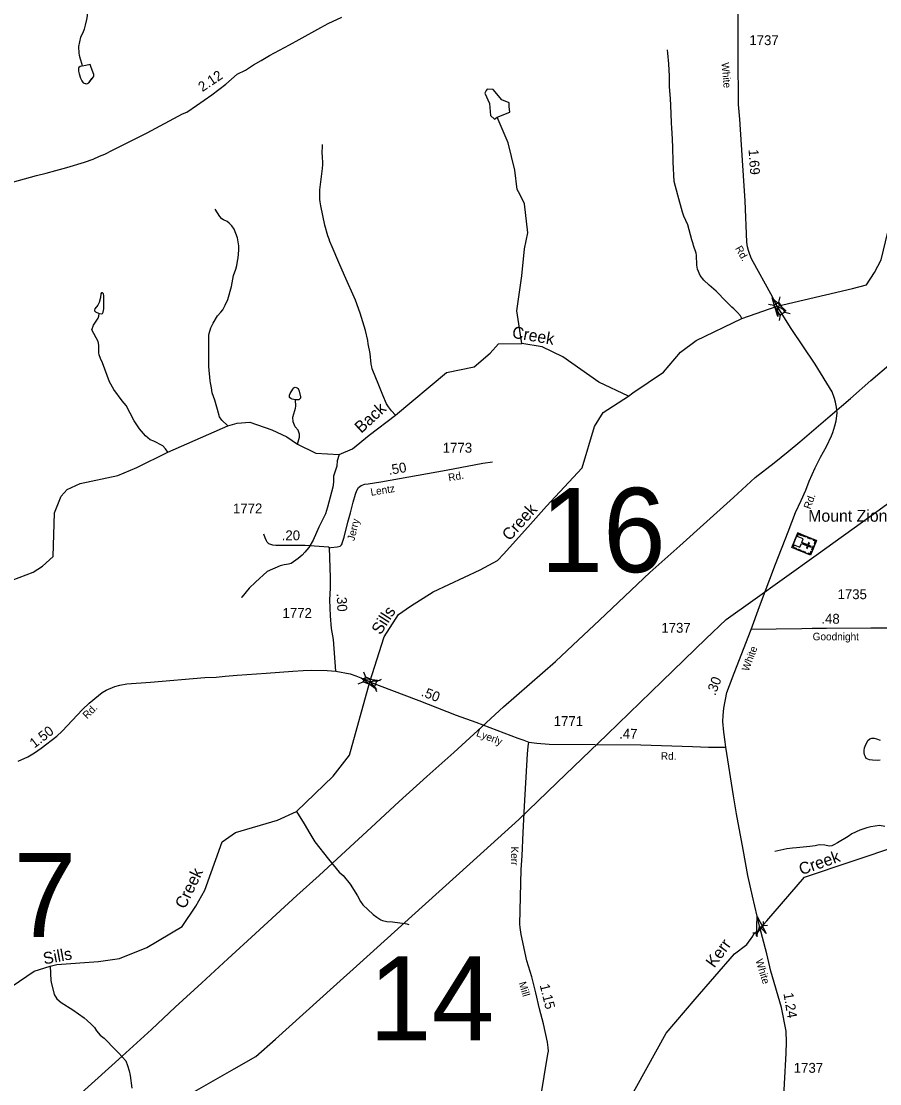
# Model space of a CAD drawing. Extents: x 1473865 to 1648260, y 639067 to 773536.
# Drawn here: x 1504347 to 1515215, y 696762 to 710204 of the extents above; entities that cross this region are included whole.
import ezdxf

# ---------------------------------------------------------------- set-up
doc = ezdxf.new("R2010")
doc.units = 0
for name, color, linetype in [('Exist Cultural Church with Cemetery CELL', 7, 'Continuous'), ('Exist Cultural Church with Cemetery Label', 7, 'Continuous'), ('Exist Hydrographic Creek Single Shore', 7, 'Continuous'), ('Exist Hydrographic Creek Single Shore Label', 7, 'Continuous'), ('Exist Hydrographic Misc Water Feature', 7, 'Continuous'), ('Exist Hydrographic Pond Under 1500 Sq Ft', 7, 'Continuous'), ('Exist Road Primary NC Attributed', 7, 'Continuous'), ('Exist Road Primary NC Mileage Hundredths English Label', 7, 'Continuous'), ('Exist Road Secondary Mileage Hundredths English Label', 7, 'Continuous'), ('Exist Road Secondary Structure Culvert CELL', 7, 'Continuous'), ('Exist Road Secondary Structure Standard Bridge Attributed CELL', 7, 'Continuous'), ('Exist Road Secondary Structure Standard Bridge CELL', 7, 'Continuous'), ('Exist Road Secondary Structure Standard Bridge Number Label', 7, 'Continuous'), ('Exist Road Secondary Type 51 Attributed', 7, 'Continuous'), ('Exist Road Secondary Type 51 Label', 7, 'Continuous'), ('Exist Road Secondary Type 51 Number Label', 7, 'Continuous'), ('Exist Utilities Electrical Transmission Line', 7, 'Continuous')]:
    doc.layers.add(name, color=color, linetype=linetype)

msp = doc.modelspace()

# ---------------------------------------------------------------- linework, layer by layer
at = {"layer": 'Exist Cultural Church with Cemetery CELL'}
for points in [[(1514414, 703635), (1514340, 703451), (1514103, 703545), (1514177, 703730)], [(1514161, 703690), (1514120, 703586), (1514204, 703552), (1514222, 703599), (1514298, 703569), (1514286, 703538), (1514296, 703534), (1514308, 703565), (1514348, 703549), (1514352, 703560), (1514313, 703576), (1514325, 703607), (1514315, 703611), (1514302, 703580), (1514227, 703610), (1514245, 703656)], [(1514165, 703699), (1514176, 703695), (1514184, 703715), (1514221, 703700), (1514225, 703711), (1514177, 703730)], [(1514242, 703704), (1514282, 703688), (1514278, 703677), (1514238, 703694)], [(1514116, 703576), (1514126, 703572), (1514118, 703551), (1514156, 703536), (1514151, 703526), (1514103, 703545)], [(1514305, 703679), (1514345, 703663), (1514340, 703652), (1514300, 703669)], [(1514386, 703567), (1514367, 703519), (1514356, 703523), (1514375, 703571)], [(1514373, 703652), (1514369, 703641), (1514399, 703629), (1514384, 703591), (1514394, 703587), (1514414, 703635)], [(1514175, 703529), (1514215, 703513), (1514211, 703502), (1514170, 703518)], [(1514236, 703504), (1514276, 703488), (1514272, 703478), (1514231, 703494)], [(1514299, 703467), (1514304, 703477), (1514333, 703465), (1514348, 703503), (1514359, 703499), (1514340, 703451)]]:
    msp.add_lwpolyline(points, close=True, dxfattribs=at)
at = {"layer": 'Exist Hydrographic Creek Single Shore'}
for points in [[(1515147, 707025), (1515233, 707185), (1515316, 707535), (1515409, 707609), (1515552, 707655), (1516048, 707642), (1516413, 707591), (1516773, 707702), (1517025, 707844), (1517253, 707977), (1517395, 708093)], [(1512035, 705463), (1512087, 705504), (1512477, 705763), (1512694, 706019), (1512892, 706164), (1513470, 706443), (1513917, 706600), (1514871, 706825), (1515045, 706871), (1515147, 707025)], [(1504232, 703135), (1504497, 703235), (1504617, 703309), (1504751, 703434), (1504768, 703986), (1504852, 704195), (1504929, 704279), (1505091, 704357), (1505568, 704456), (1505810, 704558), (1506203, 704752), (1506964, 705087), (1507079, 705119), (1507240, 705132), (1507520, 705034), (1507709, 704948), (1507844, 704852), (1508074, 704740), (1508370, 704723), (1508540, 704796), (1508751, 704966), (1509083, 705220), (1509729, 705759), (1510079, 705831), (1510283, 706006), (1510390, 706125), (1510682, 706129)], [(1512035, 705463), (1511657, 705640), (1511204, 705960), (1510940, 706084), (1510682, 706129)], [(1503949, 697809), (1504511, 698187), (1504712, 698251), (1504799, 698272), (1505326, 698309), (1505590, 698346), (1505935, 698485), (1506382, 698752), (1506556, 699011), (1506673, 699212), (1506890, 699824), (1507059, 699939), (1507589, 700099), (1507832, 700205), (1508295, 700652), (1508501, 700921), (1508761, 701848), (1508943, 702415), (1509123, 702697), (1509273, 702805), (1509562, 702986), (1510155, 703262), (1510377, 703384), (1510454, 703465), (1510793, 703843), (1510998, 704068), (1511446, 704556), (1511604, 705079), (1511715, 705256), (1512035, 705463)], [(1510085, 693408), (1510119, 693463), (1510289, 693847), (1510379, 694416), (1510415, 694624), (1510946, 695203), (1511729, 696004), (1511770, 696061), (1512510, 697403), (1512880, 697834), (1513376, 698408), (1513530, 698525), (1513610, 698628), (1513621, 698661), (1513686, 698700), (1513729, 698758), (1513744, 698775), (1513785, 698823), (1514261, 699377), (1515456, 699775), (1515889, 700003), (1516269, 700269), (1516534, 700414), (1516663, 700520)]]:
    msp.add_lwpolyline(points, dxfattribs=at)
at = {"layer": 'Exist Hydrographic Misc Water Feature'}
for points in [[(1505130, 710814), (1505126, 710734), (1505152, 710637), (1505167, 710509), (1505191, 710369), (1505181, 710273), (1505173, 710225), (1505155, 710154), (1505142, 710106), (1505128, 710058), (1505097, 710003), (1505073, 709884), (1505077, 709799), (1505080, 709775), (1505092, 709727), (1505114, 709663), (1505120, 709634)], [(1513470, 706443), (1513451, 706476), (1513416, 706518), (1513369, 706565), (1513341, 706587), (1513239, 706687), (1513172, 706760), (1513145, 706789), (1513054, 706864), (1512987, 706928), (1512940, 706986), (1512909, 707069), (1512898, 707117), (1512893, 707245), (1512889, 707269), (1512859, 707366), (1512851, 707390), (1512836, 707438), (1512787, 707627), (1512736, 707737), (1512718, 707788), (1512658, 708005), (1512613, 708178), (1512598, 708422), (1512597, 708614), (1512587, 708791), (1512583, 708846), (1512578, 708922), (1512570, 709138), (1512564, 709226), (1512555, 709374), (1512553, 709508), (1512544, 709666), (1512530, 709802), (1512527, 709842)], [(1505120, 709634), (1505110, 709635), (1505094, 709631), (1505078, 709620), (1505073, 709608), (1505073, 709572), (1505080, 709540), (1505099, 709483), (1505113, 709451), (1505132, 709427), (1505142, 709420), (1505162, 709418), (1505170, 709414), (1505186, 709418), (1505202, 709427), (1505239, 709481), (1505260, 709500), (1505264, 709508), (1505264, 709532), (1505234, 709621), (1505218, 709655), (1505166, 709646), (1505120, 709634)], [(1505120, 709634), (1505110, 709635), (1505094, 709631), (1505078, 709620), (1505073, 709608), (1505073, 709572), (1505080, 709540), (1505099, 709483), (1505113, 709451), (1505132, 709427), (1505142, 709420), (1505170, 709414), (1505186, 709418), (1505202, 709427), (1505260, 709500), (1505264, 709508), (1505264, 709532), (1505234, 709621), (1505218, 709655), (1505166, 709646), (1505120, 709634)], [(1510682, 706129), (1510622, 706539), (1510685, 706985), (1510719, 707325), (1510761, 707529), (1510719, 707894), (1510660, 708015), (1510624, 708074), (1510597, 708321), (1510509, 708666), (1510371, 708989)], [(1509083, 705220), (1509035, 705276), (1508998, 705326), (1508972, 705365), (1508924, 705474), (1508867, 705623), (1508798, 705784), (1508790, 705808), (1508783, 705832), (1508775, 705864), (1508762, 706000), (1508740, 706125), (1508733, 706165), (1508703, 706293), (1508639, 706510), (1508578, 706675), (1508441, 706986), (1508366, 707151), (1508282, 707352), (1508255, 707417), (1508243, 707449), (1508230, 707489), (1508188, 707624), (1508139, 707871), (1508132, 707919), (1508128, 707949), (1508125, 707993), (1508126, 708071), (1508159, 708342), (1508164, 708390), (1508162, 708510), (1508158, 708518), (1508159, 708646)], [(1506964, 705087), (1506888, 705156), (1506857, 705199), (1506832, 705292), (1506797, 705410), (1506764, 705502), (1506754, 705567), (1506743, 705631), (1506739, 705655), (1506723, 705835), (1506720, 706159), (1506721, 706231), (1506726, 706255), (1506745, 706326), (1506776, 706386), (1506833, 706479), (1506875, 706524), (1506897, 706555), (1506930, 706611), (1506960, 706682), (1507007, 706848), (1507035, 706988), (1507064, 707068), (1507077, 707115), (1507086, 707171), (1507091, 707211), (1507101, 707307), (1507102, 707363), (1507083, 707463), (1507041, 707572), (1507014, 707618), (1506981, 707651), (1506953, 707669), (1506907, 707690), (1506888, 707705), (1506860, 707735), (1506802, 707826)], [(1505335, 706508), (1505366, 706504), (1505374, 706508), (1505386, 706524), (1505387, 706548), (1505391, 706564), (1505394, 706732), (1505387, 706756), (1505375, 706768), (1505363, 706768), (1505353, 706756), (1505350, 706708), (1505333, 706645), (1505316, 706613), (1505279, 706566), (1505275, 706550), (1505275, 706542), (1505288, 706530), (1505335, 706508)], [(1505335, 706508), (1505366, 706504), (1505374, 706508), (1505386, 706524), (1505391, 706564), (1505394, 706732), (1505387, 706756), (1505375, 706768), (1505363, 706768), (1505353, 706756), (1505350, 706708), (1505333, 706645), (1505316, 706613), (1505279, 706566), (1505275, 706550), (1505275, 706542), (1505288, 706530), (1505335, 706508)], [(1506203, 704752), (1506174, 704794), (1506140, 704831), (1506025, 704893), (1505980, 704909), (1505919, 704959), (1505844, 705046), (1505801, 705111), (1505778, 705147), (1505726, 705247), (1505674, 705345), (1505626, 705400), (1505521, 705544), (1505463, 705643), (1505375, 705882), (1505352, 705937), (1505333, 705985), (1505329, 706009), (1505331, 706105), (1505320, 706153), (1505242, 706299), (1505263, 706358), (1505321, 706449), (1505329, 706473), (1505335, 706508)], [(1507818, 705414), (1507775, 705423), (1507759, 705430), (1507744, 705444), (1507744, 705472), (1507752, 705496), (1507783, 705551), (1507798, 705567), (1507814, 705574), (1507838, 705568), (1507846, 705564), (1507852, 705556), (1507865, 705526), (1507884, 705453), (1507883, 705437), (1507871, 705422), (1507861, 705416), (1507818, 705414)], [(1507844, 704852), (1507871, 704942), (1507871, 704982), (1507852, 705030), (1507813, 705075), (1507790, 705135), (1507783, 705197), (1507809, 705279), (1507817, 705311), (1507822, 705335), (1507818, 705414)], [(1508370, 704723), (1508345, 704641), (1508340, 704577), (1508301, 704447), (1508301, 704373), (1508291, 704310), (1508223, 704056), (1508197, 703972), (1508112, 703804), (1508043, 703640), (1507986, 703545), (1507937, 703486), (1507901, 703449), (1507851, 703407), (1507794, 703364), (1507762, 703343), (1507730, 703334), (1507706, 703330), (1507674, 703327), (1507626, 703316), (1507460, 703243), (1507314, 703108), (1507232, 703031), (1507138, 702919), (1507130, 702913)], [(1515090, 701127), (1515115, 701133), (1515142, 701135), (1515175, 701127), (1515218, 701111)], [(1515090, 701127), (1515115, 701133), (1515142, 701135), (1515175, 701127), (1515218, 701111)], [(1515220, 700858), (1515182, 700852), (1515121, 700855), (1515085, 700861), (1515062, 700867), (1515042, 700876), (1515033, 700897), (1515021, 700925), (1515016, 700951), (1515016, 700977), (1515020, 701010), (1515028, 701034), (1515051, 701080), (1515068, 701110), (1515081, 701119), (1515090, 701127)], [(1515220, 700858), (1515182, 700852), (1515121, 700855), (1515085, 700861), (1515062, 700867), (1515042, 700876), (1515033, 700897), (1515021, 700925), (1515016, 700951), (1515016, 700977), (1515020, 701010), (1515028, 701034), (1515051, 701080), (1515068, 701110), (1515090, 701127)], [(1507832, 700205), (1507929, 700052), (1508001, 699927), (1508063, 699822), (1508237, 699603), (1508372, 699441), (1508420, 699395), (1508510, 699286), (1508603, 699140), (1508640, 699067), (1508671, 699027), (1508803, 698904), (1508850, 698868), (1508900, 698835), (1508918, 698826), (1508973, 698817), (1509045, 698812), (1509141, 698798), (1509205, 698789), (1509229, 698784), (1509253, 698778)], [(1515277, 700016), (1515212, 700030), (1515100, 700012), (1515052, 700001), (1514963, 699971), (1514862, 699925), (1514814, 699890), (1514680, 699810), (1514632, 699783), (1514607, 699772), (1514575, 699768), (1514520, 699780), (1514448, 699783), (1514399, 699772), (1514331, 699763), (1514161, 699748), (1514111, 699743), (1514039, 699733), (1513926, 699711), (1513886, 699700)], [(1504712, 698251), (1504723, 698070), (1504727, 698046), (1504764, 697890), (1504796, 697836), (1504854, 697792), (1505001, 697699), (1505143, 697597), (1505182, 697564), (1505230, 697517), (1505273, 697472), (1505300, 697431), (1505347, 697379), (1505398, 697340), (1505538, 697191), (1505579, 697155), (1505669, 697053), (1505692, 696993), (1505715, 696924), (1505726, 696868), (1505747, 696708)]]:
    msp.add_lwpolyline(points, dxfattribs=at)
at = {"layer": 'Exist Hydrographic Pond Under 1500 Sq Ft'}
msp.add_lwpolyline([(1510371, 708989), (1510532, 709056), (1510525, 709125), (1510523, 709173), (1510429, 709211), (1510321, 709339), (1510245, 709343), (1510234, 709326), (1510216, 709296), (1510276, 709164), (1510288, 709013), (1510337, 708966), (1510371, 708989)], dxfattribs=at)
at = {"layer": 'Exist Road Primary NC Attributed'}
msp.add_lwpolyline([(1503805, 708050), (1504538, 708252), (1504661, 708282), (1504785, 708318), (1504923, 708354), (1505148, 708423), (1505257, 708459), (1505339, 708496), (1505404, 708524), (1505504, 708572), (1505940, 708793), (1506389, 709033), (1506441, 709054), (1506566, 709138), (1506760, 709275), (1506938, 709407), (1507082, 709535), (1507184, 709586), (1507288, 709654), (1507384, 709709), (1507489, 709770), (1507743, 709907), (1507864, 709975), (1508141, 710127), (1508231, 710176), (1508404, 710254)], dxfattribs=at)
at = {"layer": 'Exist Road Secondary Structure Culvert CELL'}
for p, q in [((1513661, 698672), (1513742, 698762)), ((1513738, 698813), (1513742, 698762)), ((1513793, 698764), (1513742, 698762)), ((1513610, 698671), (1513661, 698672)), ((1513665, 698622), (1513661, 698672))]:
    msp.add_line(p, q, dxfattribs=at)
at = {"layer": 'Exist Road Secondary Structure Standard Bridge Attributed CELL'}
for points in [[(1513924, 706470), (1513853, 706704), (1514031, 706537), (1513917, 706600)], [(1508844, 701748), (1508648, 701893), (1508890, 701865), (1508761, 701848)], [(1513654, 698634), (1513663, 698877), (1513777, 698662), (1513691, 698758)]]:
    msp.add_lwpolyline(points, close=True, dxfattribs=at)
at = {"layer": 'Exist Road Secondary Structure Standard Bridge CELL'}
for p, q in [((1513949, 706717), (1513934, 706650)), ((1513807, 706627), (1513875, 706612)), ((1514015, 706522), (1514082, 706507)), ((1513956, 706485), (1513941, 706418)), ((1508678, 701975), (1508704, 701911)), ((1508613, 701820), (1508677, 701846)), ((1508844, 701852), (1508908, 701879)), ((1508817, 701789), (1508843, 701725))]:
    msp.add_line(p, q, dxfattribs=at)
for points in [[(1513934, 706650), (1514015, 706522), (1513955, 706485), (1513875, 706612)], [(1508704, 701911), (1508844, 701853), (1508817, 701788), (1508677, 701846)]]:
    msp.add_lwpolyline(points, close=True, dxfattribs=at)
at = {"layer": 'Exist Road Secondary Type 51 Attributed'}
for points in [[(1513917, 706600), (1513838, 706757), (1513612, 707161), (1513593, 707197), (1513568, 707255), (1513552, 707302), (1513541, 707352), (1513532, 707410), (1513509, 707931), (1513495, 708185), (1513444, 708967), (1513428, 709149), (1513423, 709767), (1513422, 709976), (1513424, 710403), (1513426, 710945)], [(1513585, 702511), (1513693, 702798), (1513897, 703336), (1514054, 703746), (1514149, 703988), (1514221, 704142), (1514281, 704272), (1514323, 704385), (1514398, 704556), (1514464, 704689), (1514541, 704825), (1514603, 704958), (1514622, 705003), (1514648, 705085), (1514662, 705147), (1514677, 705244), (1514668, 705323), (1514655, 705385), (1514642, 705433), (1514612, 705514), (1514396, 705865), (1514094, 706318), (1513917, 706600)], [(1508248, 703542), (1508267, 703547), (1508348, 703554), (1508383, 703565), (1508399, 703579), (1508408, 703591), (1508411, 703602), (1508434, 703677), (1508483, 703866), (1508515, 703987), (1508549, 704119), (1508578, 704223), (1508593, 704269), (1508615, 704304), (1508650, 704332), (1508697, 704347), (1508739, 704354), (1508898, 704378), (1509725, 704526), (1510190, 704612), (1510312, 704631)], [(1508248, 703542), (1508237, 703552), (1507941, 703570), (1507629, 703570), (1507571, 703573), (1507531, 703575), (1507483, 703594), (1507462, 703614), (1507450, 703631), (1507434, 703668), (1507419, 703717)], [(1508328, 701981), (1508298, 702384), (1508276, 702520), (1508262, 702684), (1508253, 702884), (1508262, 703030), (1508262, 703166), (1508248, 703542)], [(1513265, 701021), (1513257, 701088), (1513242, 701210), (1513227, 701346), (1513233, 701422), (1513240, 701512), (1513279, 701714), (1513312, 701801), (1513372, 701956), (1513585, 702511)], [(1516098, 702457), (1515933, 702508), (1515877, 702519), (1515779, 702531), (1515421, 702524), (1515102, 702528), (1514539, 702521), (1514361, 702521), (1514230, 702519), (1513903, 702514), (1513585, 702511)], [(1504309, 700843), (1504430, 700899), (1504515, 700948), (1504599, 701006), (1504796, 701158), (1504864, 701222), (1505124, 701495), (1505207, 701577), (1505323, 701676), (1505373, 701711), (1505424, 701742), (1505532, 701787), (1505597, 701804), (1505685, 701821), (1505983, 701842), (1506670, 701900), (1506814, 701908), (1506930, 701919), (1507080, 701932), (1507446, 701955), (1507787, 701984), (1507915, 701990), (1508027, 701995), (1508220, 701991), (1508328, 701981)], [(1508328, 701981), (1508509, 701947), (1508582, 701921), (1508645, 701897), (1508733, 701861), (1508761, 701848)], [(1508761, 701848), (1508876, 701799), (1509379, 701611), (1509854, 701426), (1510101, 701337), (1510632, 701133), (1510708, 701108), (1510771, 701083)], [(1510873, 696291), (1511012, 697136), (1511021, 697176), (1511019, 697220), (1511007, 697287), (1510959, 697519), (1510907, 697710), (1510860, 697913), (1510809, 698117), (1510748, 698318), (1510676, 698652), (1510662, 698737), (1510659, 698783), (1510676, 699471), (1510687, 699645), (1510699, 699939), (1510718, 700275), (1510754, 700937), (1510762, 701030), (1510771, 701083)], [(1510771, 701083), (1510872, 701069), (1511031, 701060), (1512192, 701049), (1512846, 701028), (1513048, 701021), (1513265, 701021)], [(1513691, 698758), (1513604, 699134), (1513544, 699395), (1513485, 699725), (1513401, 700178), (1513364, 700404), (1513265, 701021)], [(1514095, 694618), (1514074, 694674), (1513960, 695001), (1513946, 695070), (1513945, 695293), (1513948, 695465), (1513972, 696020), (1514009, 696763), (1514032, 697149), (1514034, 697289), (1514029, 697426), (1513970, 697726), (1513836, 698185), (1513786, 698405), (1513691, 698758)]]:
    msp.add_lwpolyline(points, dxfattribs=at)
at = {"layer": 'Exist Utilities Electrical Transmission Line'}
for points in [[(1504940, 696497), (1505280, 696801), (1505625, 697111), (1505997, 697450), (1506294, 697731), (1506633, 698039), (1506961, 698341), (1507312, 698663), (1507836, 699142), (1508118, 699395), (1508456, 699707), (1508775, 700003), (1509129, 700331), (1509482, 700649), (1509822, 700953), (1510125, 701233), (1510450, 701530), (1510779, 701816), (1511110, 702106), (1511331, 702311), (1511666, 702629), (1512305, 703229), (1512684, 703569), (1513026, 703875), (1513363, 704181), (1513638, 704432), (1513880, 704617), (1514054, 704761), (1514203, 704885), (1514589, 705212), (1514845, 705431), (1515101, 705658), (1515358, 705879)], [(1506481, 696629), (1507041, 696952), (1507315, 697107), (1507565, 697326), (1508300, 697989), (1508634, 698287), (1509292, 698881), (1510025, 699545), (1510646, 700105), (1511127, 700570), (1511762, 701182), (1512459, 701854), (1513015, 702393), (1513272, 702636), (1513608, 702876), (1514408, 703449), (1515102, 703949), (1515773, 704433)]]:
    msp.add_lwpolyline(points, dxfattribs=at)

# ---------------------------------------------------------------- texts
at = {"layer": 'Exist Cultural Church with Cemetery Label'}
msp.add_text('Mount Zion Church', height=150, dxfattribs=at).set_placement((1514309, 703873))
at = {"layer": 'Exist Hydrographic Creek Single Shore Label'}
for s, rotation, p in [('Creek', 350.1799, (1510553, 706201)), ('Back', 42.7726, (1508651, 704984)), ('Creek', 48.0605, (1510529, 703621)), ('Sills', 57.4399, (1508896, 702432)), ('Creek', 19.3524, (1514222, 699400)), ('Creek', 64.2226, (1506420, 698964)), ('Kerr', 53.8664, (1513120, 698219)), ('Sills', 10.6234, (1504638, 698271))]:
    msp.add_text(s, height=150, rotation=rotation, dxfattribs=at).set_placement(p)
at = {"layer": 'Exist Road Primary NC Mileage Hundredths English Label'}
msp.add_text('2.12', height=125, rotation=33.9701, dxfattribs=at).set_placement((1506640, 709307))
at = {"layer": 'Exist Road Secondary Mileage Hundredths English Label'}
for s, rotation, p in [('1.69', 273.716, (1513554, 708582)), ('.50', 10.1671, (1509003, 704463)), ('.20', 359.9096, (1507644, 703638)), ('.30', 272.6004, (1508339, 702965)), ('.48', 359.4573, (1514475, 702584)), ('.30', 69.4415, (1513132, 701665)), ('.50', 338.745, (1509400, 701673)), ('1.50', 37.6486, (1504513, 701002)), ('.47', 359.4754, (1511915, 701129)), ('1.15', 284.012, (1510909, 698010)), ('1.24', 279.6029, (1513995, 697904))]:
    msp.add_text(s, height=125, rotation=rotation, dxfattribs=at).set_placement(p)
at = {"layer": 'Exist Road Secondary Structure Standard Bridge Number Label'}
for s, p in [('16', (1510919, 703235)), ('17', (1503457, 698617)), ('14', (1508749, 697310))]:
    msp.add_text(s, height=1066.3, dxfattribs=at).set_placement(p)
at = {"layer": 'Exist Road Secondary Type 51 Label'}
for s, rotation, p in [('White', 274.8721, (1513212, 709679)), ('Rd.', 299.588, (1513381, 707331)), ('Rd.', 9.9985, (1509761, 704383)), ('Lentz', 9.2983, (1508776, 704200)), ('Rd.', 69.8756, (1514336, 704024)), ('Jerry', 76.55, (1508563, 703624)), ('Goodnight', 359.9587, (1514365, 702373)), ('White', 69.4186, (1513554, 701973)), ('Rd.', 44.8821, (1505180, 701371)), ('Lyerly', 338.745, (1510099, 701164)), ('Rd.', 359.7216, (1512443, 700862)), ('Kerr', 269.5279, (1510547, 699764)), ('White', 286.8861, (1513641, 698325)), ('Mill', 286.9502, (1510643, 698038))]:
    msp.add_text(s, height=95, rotation=rotation, dxfattribs=at).set_placement(p)
at = {"layer": 'Exist Road Secondary Type 51 Number Label'}
for s, p in [('1737', (1513564, 709902)), ('1773', (1509683, 704746)), ('1772', (1507027, 703978)), ('1735', (1514680, 702893)), ('1772', (1507654, 702655)), ('1737', (1512450, 702468)), ('1771', (1511088, 701288)), ('1737', (1514126, 696901))]:
    msp.add_text(s, height=125, dxfattribs=at).set_placement(p)

doc.saveas('drawing.dxf')
